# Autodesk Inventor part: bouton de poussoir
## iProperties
Author: chr
Created: 2002-03
Part Number: bouton de poussoir
Material: Par défaut
Document SubType Name: Modélisation
Designer: chr
Control State: 0
Master: False
Checked Out: False
PropertySet Name: Design Tracking Control
Shininess: 20.0
Angle Display Precision: 2
Document Length Units: 11269
Document Angle Units: 11283
Document Time Units: 11279
Document Mass Units: 11290
Document Length Units Precision: 3
Document Angle Units Precision: 2
Compacted: False
PropertySet Name: _Private Model Information
Density: 0.0
Volumn: 0.0
Area: 0.0
PropertySet Name: Model Information
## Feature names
1. Extrusion1
2. Extrusion2
